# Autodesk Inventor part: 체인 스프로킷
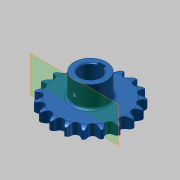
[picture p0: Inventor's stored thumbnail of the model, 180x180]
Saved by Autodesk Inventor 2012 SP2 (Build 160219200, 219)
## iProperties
Created: 2014-11
Part Number: 체인 스프로킷
Material: 강
Document SubType Name: Modeling
Designer: KYOUNG IL JANG
Density: 7.85 g/cm^3
Mass: 738.264 g
Surface Area: 236.923 cm^2
Volume: 94.0463 cm^3
CustomPartVersion: 1
Company: 한국ATC센터
Author: KYOUNG IL JANG
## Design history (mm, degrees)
sketch "이론적 톱니 프로파일"
  geometry: L1 (0, 0)-(0, 45.567); L2 (0, 0)-(14.795, 43.098); L3 (0, 45.567)-(14.795, 43.098); L4 (0, 45.567)-(5.661, 50.015); L5 (5.661, 50.015)-(-5.141, 45.406); L6 (-12.428, 43.493)-(-5.573, 46.417); L7 (-5.141, 45.406)-(-5.573, 46.417); L8 (5.573, 46.417)-(5.141, 45.406); L9 (0, 0)-(8.138, 48.771); A1 r 45.567 centre (0, 0) between (0, 45.567) and (14.795, 43.098); A2 r 49.445 centre (0, 0) between (7.302, 48.903) and (-7.302, 48.903); A3 r 4.545 centre (0, 45.567) between (-3.574, 42.758) and (3.574, 42.758); A4 r 7.453 centre (12.428, 43.493) between (7.302, 48.903) and (5.573, 46.417); A5 r 7.453 centre (-12.428, 43.493) between (-5.573, 46.417) and (-7.302, 48.903); A6 r 11.745 centre (5.661, 50.015) between (-5.141, 45.406) and (-3.574, 42.758); A7 r 11.745 centre (-5.661, 50.015) between (3.574, 42.758) and (5.141, 45.406); 2 further points
  constraints: 18 end point, 15 point on circle, 7 centre point, 3 coincident, 3 point on line, 3 symmetric about line, 3 tangent, 1 equal radius, 1 midpoint, 1 parallel, 1 vertical, 1 other
  dimensions: "d0" = 91.13301 diameter of A1 (computed from da_p, da_z); "d2" = 18.9474 deg angle of L2 L1 (computed from da_z); "d3" = 4.545 radius of A3 (= 0.5 x da_Dr + da_SC); "d10" = 128.158 deg angle of L4 L1 (computed from da_z); "d11" = 15.0526 deg angle of L5 L4 (computed from da_z); "d12" = 7.2 distance of L3.start L4.end (= 0.8 x da_Dr); "d13" = 11.745 distance of L4.end L5.end (= 1.3 x da_Dr + da_SC); "d14" = 12.6 distance of A4.centre L1.end (= 1.4 x da_Dr); "d23" = 4.5 distance from line of L9.end L3 (= da_Ha)
sketch "톱니 프로파일"
  geometry: L1 (0, 0)-(0, 45.567); L2 (0, 45.567)-(4.203, 43.837); L3 (0, 45.567)-(-4.203, 43.837); A1 r 4.545 centre (0, 45.567) between (-4.203, 43.837) and (4.203, 43.837); A2 r 22.68 centre (25.176, 35.206) between (7.12, 48.93) and (4.203, 43.837); A3 r 22.68 centre (-25.176, 35.206) between (-4.203, 43.837) and (-7.12, 48.93); A4 r 49.445 centre (0, 0) between (-7.12, 48.93) and (7.12, 48.93) reference; 1 further point
  constraints: 9 point on circle, 6 end point, 3 centre point, 2 tangent, 1 coincident, 1 equal radius, 1 vertical, 1 other
  dimensions: "d44" = 135.263 deg angle of L3 L2 (= da_Alfa); "d45" = 22.68 radius of A2 (= da_Re); "d46" = 4.545 radius of A1 (= da_Ri)
sketch "단면 프로파일"
  geometry: L1 (49.445, 0)-(-49.445, 0) reference; L2 (33.265, 6.65)-(-33.265, 6.65); L3 (-33.265, 6.65)-(-33.265, -6.65); L4 (-33.265, -6.65)-(33.265, -6.65); L5 (33.265, -6.65)-(33.265, 6.65); L6 (33.265, 6.65)-(49.445, 6.65); L7 (49.445, 6.65)-(49.445, -6.65); L8 (49.445, -6.65)-(33.265, -6.65); L9 (33.265, -6.65)-(33.265, 6.65); L10 (42.183, 6.65)-(0, 6.65); L11 (0, 6.65)-(0, -6.65); L12 (0, -6.65)-(42.183, -6.65); L13 (0, 6.65)-(0, -6.65); L14 (49.445, 4.775)-(49.445, -4.775); A1 r 15 centre (42.183, -8.35) between (49.445, 4.775) and (42.183, 6.65); A2 r 15 centre (42.183, 8.35) between (42.183, -6.65) and (49.445, -4.775); 2 further points
  constraints: 26 end point, 7 midpoint, 5 perpendicular, 4 parallel, 4 point on circle, 3 point on line, 3 symmetric about line, 2 centre point, 2 horizontal, 2 tangent, 1 collinear, 1 other
  dimensions: "d30" = 13.3 distance between parallel lines of L8 L6 (= da_Bf); "d31" = 66.53007 distance between parallel lines of L3 L5 (= da_Ds); "d32" = 13.3 distance between parallel lines of L4 L2 (= da_Bs); "d33" = 1.875 distance from line of L14.start L6 (= da_Ba); "d34" = 15 radius of A1 (= da_Rx); "d43" = 6.65 distance between parallel lines of L4 L1 (computed from da_k, da_pt, da_Bs)
revolve "슈라우드" stored, may be unused: angle "d36" = 90 deg
revolve "스트랜드" stored, may be unused: angle "d37" = 90 deg
extrude "이론적 톱니" cut sketch "이론적 톱니 프로파일" stored distance "d18" = 10; taper "d19" = 0 deg; dims "d49" = 0, "form_type" = 0 [user parameter]
extrude "톱니" cut sketch "톱니 프로파일" stored distance "d47" = 10; taper "d48" = 0 deg; dims "d50" = 10, "form_type" = 0 [user parameter]
node "타이밍 평면"
node "작업 평면3"
sketch "스케치5"
  geometry: C1 r 20 at (0, -45.567); 1 further point
  constraints: 1 centre point, 1 coincident
  dimensions: "d52" = 40 diameter of C1
extrude "돌출4" join sketch "스케치5" stored distance "d53" = 10; taper "d54" = 0 deg
sketch "스케치6"
  geometry: L1 (4, 11.843)-(4, 16.5); L2 (4, 16.5)-(-4, 16.5); L3 (-4, 16.5)-(-4, 11.843); A1 r 12.5 centre (0, 0) between (4, 11.843) and (-4, 11.843); 1 further point
  constraints: 6 end point, 2 parallel, 2 point on circle, 1 centre point, 1 coincident, 1 perpendicular, 1 vertical
  dimensions: "d55" = 25 diameter of A1; "d56" = 29 dimension on A1 L2 (computed from d55); "d57" = 8 distance of L1.end L2.end
extrude "돌출5" cut sketch "스케치6" stored distance "d58" = 10; taper "d59" = 0 deg
fillet "모깎기2" dims "d60" = 3
chamfer "모따기1" distance "d61" = 1; stored, may be unused: second distance "d62" = 2, angle "d63" = 45 deg
node "작업 평면4"
sketch "스케치7"
  geometry: L1 (-13.5, -13.3)-(13.5, -13.3) reference; 4 further points
  constraints: 1 vertical alignment
  dimensions: "d65" = 25 distance from line of point (0, 11.7) L1
hole "구멍1" sketch "스케치7" at (0, 11.7) diameter "d66" = 5; stored, may be unused: countersink angle "d70" = 90 deg, drill point angle "d72" = 118 deg; dims "d67" = 6, "d68" = 4, "d69" = 2, "d71" = 8
feature "스레드1" dims "d73" = 10, "d74" = 0
body "Solid1"
pattern_linear "스트랜드 패턴" dims "d40" = 24 (= da_pt)
pattern_circular "톱니 패턴" dims angle "d21" = 360 deg
other parameters: "da_p" = 15 [user parameter; used in 1 equation term], "da_Dr" = 9 [user parameter; used in 4 equation terms], "da_SC" = 0.045 [user parameter; used in 2 equation terms], "da_Ha" = 4.5 [user parameter; used in 1 equation term], "da_pt" = 24 [user parameter; used in 2 equation terms], "da_Bf" = 13.3 [user parameter; used in 1 equation term], "d28" = 0, "d29" = 0, "da_Ba" = 1.875 [user parameter; used in 1 equation term], "da_Rx" = 15 [user parameter; used in 1 equation term], "da_Ra" = 0.6 [user parameter], "da_Bs" = 13.3 [user parameter; used in 2 equation terms], "da_Ds" = 66.53007 [user parameter; used in 1 equation term], "d42" = 0, "da_Re" = 22.68 [user parameter; used in 1 equation term], "da_Ri" = 4.545 [user parameter; used in 1 equation term], "da_Alfa" = 135.263 deg [user parameter; used in 1 equation term]
